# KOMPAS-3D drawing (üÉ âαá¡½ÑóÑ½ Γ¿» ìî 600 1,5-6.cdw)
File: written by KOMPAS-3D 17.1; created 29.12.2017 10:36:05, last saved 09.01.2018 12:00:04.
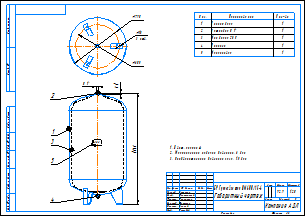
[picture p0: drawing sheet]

Sheet 1: A3, landscape, title-block layout from C:\Лощинин\GRAPHIC.LYT style 1

Title block, sheet 1: name: БР Гранлевел тип НМ 600/1,5-6 / Габаритный чертеж; mass: 92,9; sheets: 1; sheet format: A3; stored path: \\Fsk1\files\АП\20_PKO\02_Насосное направление\Разработка\04_Проекты разные\Баки\КД действующая\Баки Flexcon R\Компас\Чертежи\БР Гранлевел тип НМ 600 1,5-6.cdw; drawn by: Лощинин; checked by: Хантимеров

Views: Проекционный вид 2
Referenced files in \\Fsk1\files\АП\20_PKO\02_Насосное направление\Разработка\04_Проекты разные\Баки\КД действующая\Баки Flexcon R\Компас\: 600 литров.a3d, 16602_Flexcon_600_1-6.m3d
Referenced files in C:\Лощинин\: GRAPHIC.LYT
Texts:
  IvAn
  ADL
  Поз.
  Кол-во
  Корпус бака
  Мембрана SBR
  Патрубок G 1"
  Ниппель
  Маркировка
  АДЛ
  Цвет: красный
  Максимальное рабочее давление: 6 бар
  Предварительное давление газа: 1,5 бар
  ACAD_ISO03W100_RGB_223_127_255_SC_0.063_THICK_0.05
  ACAD_ISO03W100_RGB_223_127_255_SC_1_THICK_0.05
  Лит-Масса-Масштаб
  Материал-Предприятие
  Масштаб
  Изм.
  Лист
  № докум.
  Подп.
  Дата
  Лит.
  Разраб.
  Пров.
  Т.контр.
  Курлыкина
  Листов
  Нач.отд.
  Щетинин
  Н.контр.
  Долгов
  Утв.
  Рашидов
  Компания АДЛ
  Изменение
  Номер документа
  Подпись
  Обозначение документа
  Наименование изделия
  Масса изделия по ГОСТ 2.109-73
  Порядковый номер листа
  Общее количество листов в документе
  Характер работы, выполненной лицом, подписавшим документ
  Наименование или индекс предприятия, выпускающего документ
  Инв. № подл.
  Подп. и дата
  Взам. инв. №
  Инв. № дубл.
  Инвентарный номер подлинника по ГОСТ 2.501-68
  Подпись принявшего подлинник в отдел технической документации
  Инвентарный номер подлинника, взамен которого выпущен данный подлинник
  Инвентарный номер дубликата по ГОСТ 2.502-68
  Подпись принявшего дубликат в отдел технической документации
  Справ. №
  Перв. примен.
  Обозначение документа, взамен или на основании которого выпущен данный документ
  Обозначение документа, в котором впервые записан данный документ
  Подпись лица, копировавшего чертеж
  Обозначение формата листа
Dimensions and other numbers on the sheet: 1; 3; 2; 4; 5; 1540; 21; 1:20; 92,9; 16602_Flexcon_600_1-6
